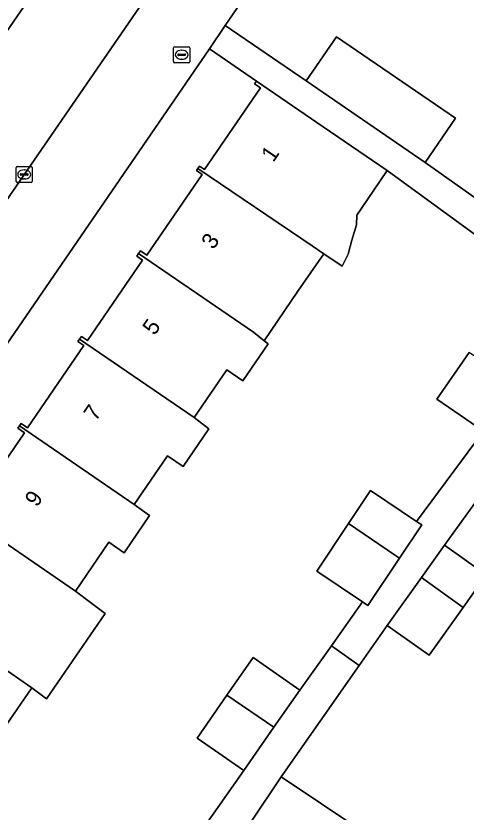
# Model space of a CAD drawing. Extents: x 160157 to 160921, y 381516 to 382045.
# Drawn here: x 160692.23 to 160720.08, y 381759.62 to 381808.91 of the extents above; entities that cross this region are included whole.
import ezdxf

# ---------------------------------------------------------------- set-up
doc = ezdxf.new("R2010")
doc.units = 0
for name, color, linetype in [('IMGEO_Brandkraan', 7, 'Continuous'), ('IMGEO_Erf', 7, 'Continuous'), ('IMGEO_Kolk', 7, 'Continuous'), ('IMGEO_Pand', 7, 'Continuous'), ('IMGEO_Pand_nummerreeks', 7, 'Continuous'), ('IMGEO_Rijbaan_lokaal_open', 7, 'Continuous'), ('IMGEO_Voetpad_halfverhard', 7, 'Continuous'), ('IMGEO_Voetpad_open', 7, 'Continuous')]:
    doc.layers.add(name, color=color, linetype=linetype)

msp = doc.modelspace()

# ---------------------------------------------------------------- linework, layer by layer
at = {"layer": 'IMGEO_Brandkraan'}
for p, q in [((160701.986, 381806.075), (160701.986, 381806.927)), ((160702.061, 381807.001), (160702.913, 381807.001)), ((160702.474, 381806.781), (160702.499, 381806.781)), ((160702.987, 381806.927), (160702.987, 381806.075)), ((160702.245, 381806.495), (160702.245, 381806.507)), ((160702.683, 381806.458), (160702.285, 381806.458)), ((160702.288, 381806.544), (160702.686, 381806.544)), ((160702.497, 381806.221), (160702.472, 381806.221)), ((160702.729, 381806.507), (160702.729, 381806.495)), ((160702.913, 381806.001), (160702.061, 381806.001))]:
    msp.add_line(p, q, dxfattribs=at)
for points in [[(160701.986, 381806.075), (160701.986, 381806.927)], [(160702.061, 381807.001), (160702.913, 381807.001)], [(160702.987, 381806.927), (160702.987, 381806.075)], [(160702.913, 381806.001), (160702.061, 381806.001)]]:
    msp.add_lwpolyline(points, dxfattribs=at)
for centre, radius, start, end in [((160702.063, 381806.925), 0.0765, 91.552, 178.448), ((160702.063, 381806.925), 0.0765, 91.552, 178.448), ((160702.911, 381806.925), 0.0765, 1.552, 88.448), ((160702.911, 381806.925), 0.0765, 1.552, 88.448), ((160702.285, 381806.504), 0.0403, 85.8775, 175.7526), ((160702.282, 381806.494), 0.0366, 178.938, 274.7102), ((160702.686, 381806.501), 0.043, 264.8664, 352.4533), ((160702.69, 381806.506), 0.0386, 1.7309, 96.639), ((160702.063, 381806.077), 0.0765, 181.552, 268.448), ((160702.063, 381806.077), 0.0765, 181.552, 268.448), ((160702.911, 381806.077), 0.0765, 271.552, 358.448), ((160702.911, 381806.077), 0.0765, 271.552, 358.448)]:
    msp.add_arc(centre, radius, start, end, dxfattribs=at)
for centre, major_axis, ratio, start_param, end_param in [((160702.473, 381806.501), (-0.387, 0.002), 0.722429, 4.712389, 7.853982), ((160702.498, 381806.501), (-0.39, 0.002), 0.717154, 1.570796, 4.712389)]:
    msp.add_ellipse(centre, major_axis=major_axis, ratio=ratio, start_param=start_param, end_param=end_param, dxfattribs=at)
at = {"layer": 'IMGEO_Erf'}
for points in [[(160719.08, 381828.577), (160705.185, 381808.313), (160710.181, 381804.887), (160712.056, 381807.621), (160719.424, 381802.569), (160717.549, 381799.835), (160729.351, 381791.476)], [(160689.306, 381778.051), (160692.767, 381783.099), (160692.351, 381783.385), (160692.453, 381783.534), (160692.555, 381783.683), (160692.947, 381783.415), (160696.433, 381788.498), (160696.067, 381788.749), (160696.176, 381788.907), (160696.285, 381789.067), (160696.659, 381788.81), (160700.068, 381793.782), (160699.709, 381794.028), (160699.825, 381794.197), (160699.941, 381794.365), (160700.326, 381794.1), (160703.749, 381799.091), (160703.401, 381799.33), (160703.497, 381799.471), (160703.593, 381799.61), (160703.901, 381799.399), (160707.362, 381804.446), (160706.999, 381804.694), (160707.123, 381804.875), (160704.201, 381806.878), (160674.789, 381763.984)], [(160726.766, 381790.897), (160715.209, 381799.331), (160713.593, 381796.974), (160713.313, 381796.566), (160713.304, 381795.975), (160713.016, 381795.03), (160712.784, 381794.163), (160712.408, 381793.418), (160711.277, 381794.186), (160709.681, 381791.859), (160707.585, 381788.801), (160707.831, 381788.604), (160706.271, 381786.328), (160705.291, 381786.999), (160703.265, 381784.045), (160704.175, 381783.352), (160702.578, 381781.024), (160701.618, 381781.683), (160699.549, 381778.667), (160700.499, 381777.973), (160698.926, 381775.679), (160697.988, 381776.322), (160695.912, 381773.294), (160696.84, 381772.6), (160697.757, 381771.914), (160694.13, 381766.627), (160693.214, 381767.308), (160691.629, 381764.996)], [(160739.356, 381750), (160751.191, 381767.158), (160753.822, 381770.972), (160735.153, 381783.849), (160727.618, 381789.046), (160725.558, 381786.168), (160731.355, 381782.148), (160728.591, 381778.227), (160729.581, 381777.174), (160727.057, 381775.795), (160721.421, 381779.855), (160718.748, 381776.145), (160721.334, 381774.3), (160719.892, 381772.28), (160717.79, 381769.334), (160715.204, 381771.179), (160713.472, 381768.708), (160708.643, 381761.815), (160716.195, 381756.759)], [(160702.195, 381756.292), (160706.329, 381762.2), (160703.444, 381764.21), (160705.291, 381766.861), (160706.912, 381769.187), (160709.796, 381767.178), (160711.747, 381769.917), (160713.682, 381772.634), (160710.839, 381774.536), (160712.817, 381777.494), (160714.173, 381779.521), (160717.018, 381777.619), (160721.15, 381783.205), (160718.278, 381785.174), (160720.269, 381788.078)]]:
    msp.add_lwpolyline(points, dxfattribs=at)
at = {"layer": 'IMGEO_Kolk'}
for p, q in [((160692.246, 381798.666), (160692.246, 381799.518)), ((160692.321, 381799.592), (160693.173, 381799.592)), ((160692.734, 381799.372), (160692.759, 381799.372)), ((160693.247, 381799.518), (160693.247, 381798.666)), ((160692.505, 381799.086), (160692.505, 381799.098)), ((160692.943, 381799.049), (160692.545, 381799.049)), ((160692.548, 381799.135), (160692.946, 381799.135)), ((160692.989, 381799.098), (160692.989, 381799.086)), ((160693.173, 381798.592), (160692.321, 381798.592)), ((160692.757, 381798.812), (160692.732, 381798.812))]:
    msp.add_line(p, q, dxfattribs=at)
for points in [[(160692.246, 381798.666), (160692.246, 381799.518)], [(160692.321, 381799.592), (160693.173, 381799.592)], [(160693.247, 381799.518), (160693.247, 381798.666)], [(160693.173, 381798.592), (160692.321, 381798.592)]]:
    msp.add_lwpolyline(points, dxfattribs=at)
for centre, radius, start, end in [((160692.323, 381799.516), 0.0765, 91.552, 178.448), ((160692.323, 381799.516), 0.0765, 91.552, 178.448), ((160693.171, 381799.516), 0.0765, 1.552, 88.448), ((160693.171, 381799.516), 0.0765, 1.552, 88.448), ((160692.545, 381799.095), 0.0403, 85.8775, 175.7526), ((160692.542, 381799.085), 0.0366, 178.938, 274.7102), ((160692.946, 381799.092), 0.043, 264.8664, 352.4533), ((160692.95, 381799.097), 0.0386, 1.7309, 96.639), ((160692.323, 381798.668), 0.0765, 181.552, 268.448), ((160692.323, 381798.668), 0.0765, 181.552, 268.448), ((160693.171, 381798.668), 0.0765, 271.552, 358.448), ((160693.171, 381798.668), 0.0765, 271.552, 358.448)]:
    msp.add_arc(centre, radius, start, end, dxfattribs=at)
for centre, major_axis, ratio, start_param, end_param in [((160692.733, 381799.092), (-0.387, 0.002), 0.722429, 4.712389, 7.853982), ((160692.758, 381799.092), (-0.39, 0.002), 0.717154, 1.570796, 4.712389)]:
    msp.add_ellipse(centre, major_axis=major_axis, ratio=ratio, start_param=start_param, end_param=end_param, dxfattribs=at)
at = {"layer": 'IMGEO_Pand'}
for points in [[(160717.549, 381799.835), (160719.424, 381802.569), (160712.056, 381807.621), (160710.181, 381804.887)], [(160711.247, 381802.048), (160707.123, 381804.875), (160706.999, 381804.694), (160707.362, 381804.446), (160703.901, 381799.399), (160703.593, 381799.61), (160703.497, 381799.471), (160710.569, 381794.667), (160711.277, 381794.186), (160712.408, 381793.418), (160712.784, 381794.163), (160713.016, 381795.03), (160713.304, 381795.975), (160713.313, 381796.566), (160713.593, 381796.974), (160715.209, 381799.331)], [(160710.569, 381794.667), (160703.497, 381799.471), (160703.401, 381799.33), (160703.749, 381799.091), (160700.326, 381794.1), (160699.941, 381794.365), (160699.825, 381794.197), (160706.923, 381789.329), (160707.585, 381788.801), (160709.681, 381791.859), (160711.277, 381794.186)], [(160706.923, 381789.329), (160699.825, 381794.197), (160699.709, 381794.028), (160700.068, 381793.782), (160696.659, 381788.81), (160696.285, 381789.067), (160696.176, 381788.907), (160703.265, 381784.045), (160705.291, 381786.999), (160706.271, 381786.328), (160707.831, 381788.604), (160707.585, 381788.801)], [(160696.176, 381788.907), (160696.067, 381788.749), (160696.433, 381788.498), (160692.947, 381783.415), (160692.555, 381783.683), (160692.453, 381783.534), (160699.549, 381778.667), (160701.618, 381781.683), (160702.578, 381781.024), (160704.175, 381783.352), (160703.265, 381784.045)], [(160723.476, 381785.899), (160723.237, 381786.062), (160720.269, 381788.078), (160718.278, 381785.174), (160721.15, 381783.205), (160721.476, 381782.981)], [(160688.819, 381778.159), (160695.912, 381773.294), (160697.988, 381776.322), (160698.926, 381775.679), (160700.499, 381777.973), (160699.549, 381778.667), (160692.453, 381783.534), (160692.351, 381783.385), (160692.767, 381783.099), (160689.306, 381778.051), (160688.925, 381778.312)], [(160712.817, 381777.494), (160715.651, 381775.55), (160715.956, 381775.341), (160717.337, 381777.405), (160717.018, 381777.619), (160714.173, 381779.521)], [(160685.131, 381772.905), (160693.214, 381767.308), (160694.13, 381766.627), (160697.757, 381771.914), (160696.84, 381772.6), (160695.912, 381773.294), (160688.819, 381778.159), (160688.715, 381778.007), (160689.068, 381777.765), (160685.647, 381772.775), (160685.235, 381773.057)], [(160712.817, 381777.494), (160710.839, 381774.536), (160713.682, 381772.634), (160714.003, 381772.42), (160715.956, 381775.341), (160715.651, 381775.55)], [(160719.892, 381772.28), (160721.334, 381774.3), (160718.748, 381776.145), (160717.328, 381774.155)], [(160719.892, 381772.28), (160717.328, 381774.155), (160715.204, 381771.179), (160717.79, 381769.334)], [(160685.131, 381772.905), (160685.029, 381772.756), (160685.454, 381772.465), (160682.003, 381767.432), (160681.622, 381767.694), (160681.518, 381767.542), (160688.635, 381762.661), (160690.682, 381765.646), (160691.629, 381764.996), (160693.214, 381767.308)], [(160705.291, 381766.861), (160708.19, 381764.872), (160709.796, 381767.178), (160706.912, 381769.187)], [(160705.291, 381766.861), (160703.444, 381764.21), (160706.329, 381762.2), (160708.19, 381764.872)], [(160709.333, 381757.185), (160710.649, 381756.304), (160714.289, 381753.867), (160716.195, 381756.759), (160708.643, 381761.815), (160706.757, 381758.998)]]:
    msp.add_lwpolyline(points, close=True, dxfattribs=at)
at = {"layer": 'IMGEO_Rijbaan_lokaal_open'}
msp.add_lwpolyline([(160658.96, 381750), (160667.503, 381762.414), (160670.296, 381766.471), (160700.524, 381810.394), (160703.573, 381814.824), (160712.504, 381827.801), (160716.028, 381832.837), (160716.089, 381833.009), (160711.248, 381836.325), (160711.08, 381836.076), (160707.501, 381830.956), (160699.651, 381819.545), (160692.328, 381808.901), (160680.332, 381791.464), (160678.334, 381788.56), (160651.806, 381750)], dxfattribs=at)
at = {"layer": 'IMGEO_Voetpad_halfverhard'}
for points in [[(160729.351, 381791.476), (160717.549, 381799.835), (160710.181, 381804.887), (160705.185, 381808.313), (160704.201, 381806.878), (160707.123, 381804.875), (160711.247, 381802.048), (160715.209, 381799.331), (160726.766, 381790.897)], [(160721.15, 381783.205), (160717.018, 381777.619), (160717.337, 381777.405), (160715.956, 381775.341), (160714.003, 381772.42), (160713.682, 381772.634), (160711.747, 381769.917), (160713.472, 381768.708), (160715.204, 381771.179), (160717.328, 381774.155), (160718.748, 381776.145), (160721.421, 381779.855)]]:
    msp.add_lwpolyline(points, dxfattribs=at)
at = {"layer": 'IMGEO_Voetpad_open'}
msp.add_lwpolyline([(160707.501, 381830.956), (160711.08, 381836.076), (160711.248, 381836.325), (160707.078, 381835.076), (160693.176, 381814.897), (160692.079, 381813.304), (160675.928, 381789.86), (160675.328, 381788.989), (160648.467, 381750), (160641.671, 381740.128), (160640.592, 381738.561), (160605.905, 381688.17), (160606.806, 381684.4), (160609.452, 381688.229), (160610.996, 381690.462), (160614.441, 381695.549), (160641.13, 381734.448), (160643.136, 381737.367), (160651.806, 381750), (160678.334, 381788.56), (160680.332, 381791.464), (160692.328, 381808.901), (160699.651, 381819.545)], close=True, dxfattribs=at)
for points in [[(160716.089, 381833.009), (160716.028, 381832.837), (160712.504, 381827.801), (160703.573, 381814.824), (160700.524, 381810.394), (160670.296, 381766.471), (160667.503, 381762.414), (160658.96, 381750), (160642.496, 381725.9), (160640.187, 381722.521), (160619.05, 381691.582), (160615.999, 381687.121), (160614.454, 381684.835), (160611.203, 381680.025), (160615.694, 381677.246), (160615.835, 381678.381), (160616.408, 381679.37), (160644.455, 381719.97), (160645.316, 381721.217), (160665.2, 381750)], [(160665.2, 381750), (160672.541, 381760.705), (160673.051, 381761.449), (160674.255, 381763.205), (160674.789, 381763.984), (160704.201, 381806.878), (160705.185, 381808.313), (160719.08, 381828.577)], [(160706.757, 381758.998), (160708.643, 381761.815), (160713.472, 381768.708), (160711.747, 381769.917), (160709.796, 381767.178), (160708.19, 381764.872), (160706.329, 381762.2), (160702.195, 381756.292)]]:
    msp.add_lwpolyline(points, dxfattribs=at)

# ---------------------------------------------------------------- texts
at = {"layer": 'IMGEO_Pand_nummerreeks'}
for s, rotation, p in [('1', 55.5884, (160708.157, 381799.802)), ('3', 55.5884, (160704.453, 381794.395)), ('5', 55.5884, (160700.814, 381789.082)), ('7', 55.5882, (160697.174, 381783.77)), ('9', 55.5882, (160693.535, 381778.457))]:
    msp.add_text(s, height=1, rotation=rotation, dxfattribs=at).set_placement(p)

doc.saveas('drawing.dxf')
